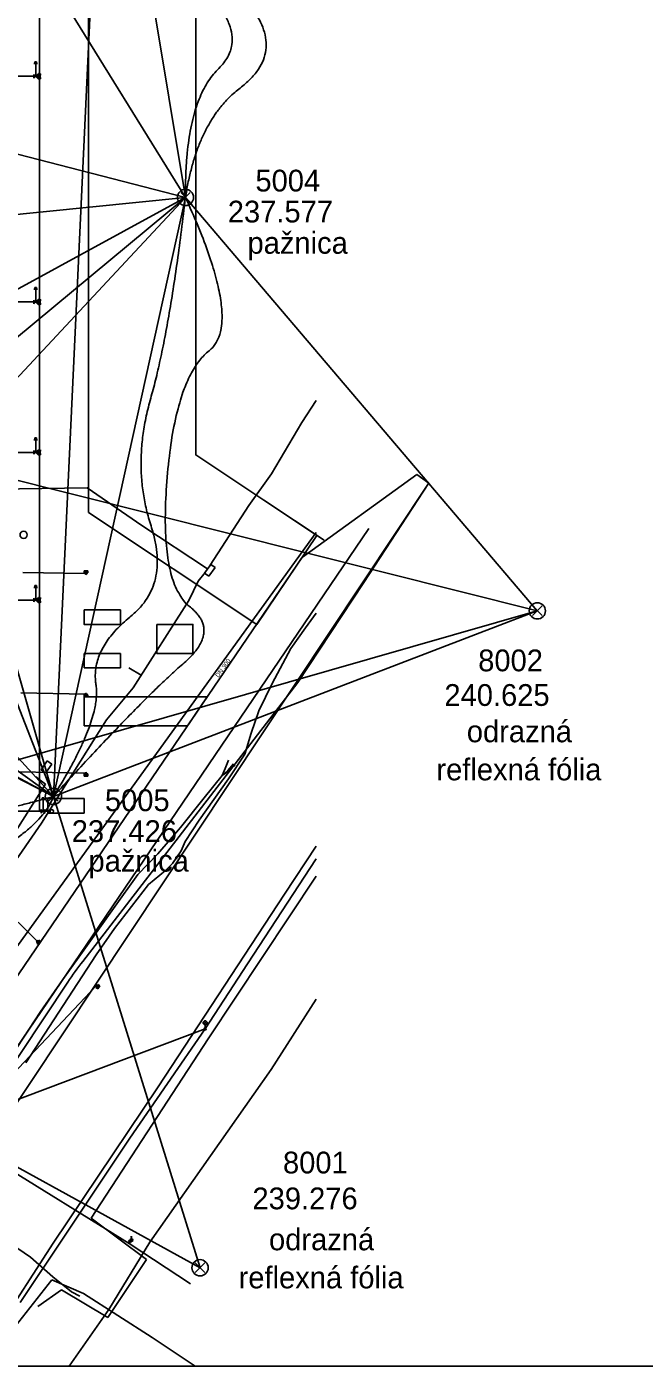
# Model space of a CAD drawing. Extents: x -264090 to -263500, y -1242327 to -1242030.
# Drawn here: x -263789.9 to -263704.8, y -1242326.6 to -1242142 of the extents above; entities that cross this region are included whole.
import ezdxf

# ---------------------------------------------------------------- set-up
doc = ezdxf.new("R2010")
doc.units = 0
for name, color, linetype in [('KFA_KOORD_SIT_a_IS_SEDA', 7, 'Continuous'), ('KFA_ZVS_BOD_CISLO', 7, 'Continuous'), ('KFA_ZVS_BOD_SYMBOL', 7, 'Continuous'), ('KFA_ZVS_BOD_VYSKA', 7, 'Continuous'), ('KFA_ZVS_NIVELACIA', 7, 'Continuous'), ('KFA_ZVS_POPIS', 7, 'Continuous'), ('KFA_ZVS_SMERY_A_DLZKY', 7, 'Continuous'), ('RAM_NA_TLAC', 7, 'Continuous')]:
    doc.layers.add(name, color=color, linetype=linetype)

msp = doc.modelspace()

# ---------------------------------------------------------------- linework, layer by layer
at = {"layer": 'KFA_KOORD_SIT_a_IS_SEDA'}
for p, q in [((-263766.58, -1242144.85), (-263766.58, -1242074.39)), ((-263788.14, -1242250.14), (-263788.14, -1242082.64)), ((-263766.58, -1242201.01), (-263766.58, -1242144.85)), ((-263788.77, -1242147.08), (-263788.89, -1242147.08)), ((-263788.77, -1242146.83), (-263788.77, -1242147.08)), ((-263788.52, -1242146.83), (-263788.77, -1242146.83)), ((-263788.64, -1242148.83), (-263788.64, -1242146.96)), ((-263788.52, -1242147.08), (-263788.52, -1242146.83)), ((-263788.52, -1242147.08), (-263788.39, -1242147.08)), ((-263788.89, -1242148.83), (-263800.59, -1242148.83)), ((-263788.89, -1242148.58), (-263788.89, -1242149.08)), ((-263788.39, -1242149.08), (-263788.89, -1242148.58)), ((-263788.89, -1242149.08), (-263788.39, -1242148.58)), ((-263788.39, -1242148.58), (-263788.39, -1242149.08)), ((-263788.39, -1242148.58), (-263787.89, -1242148.58)), ((-263788.14, -1242148.83), (-263788.39, -1242148.83)), ((-263788.39, -1242148.83), (-263788.14, -1242148.83)), ((-263788.39, -1242149.08), (-263787.89, -1242149.08)), ((-263788.27, -1242148.46), (-263788.27, -1242149.21)), ((-263788.02, -1242148.46), (-263788.27, -1242148.46)), ((-263788.02, -1242149.21), (-263788.02, -1242148.46)), ((-263788.27, -1242149.21), (-263788.02, -1242149.21)), ((-263788.77, -1242178.18), (-263788.89, -1242178.18)), ((-263788.77, -1242177.93), (-263788.77, -1242178.18)), ((-263788.52, -1242177.93), (-263788.77, -1242177.93)), ((-263788.64, -1242179.93), (-263788.64, -1242178.06)), ((-263788.52, -1242178.18), (-263788.52, -1242177.93)), ((-263788.52, -1242178.18), (-263788.39, -1242178.18)), ((-263788.89, -1242179.93), (-263800.59, -1242179.93)), ((-263788.89, -1242179.68), (-263788.89, -1242180.18)), ((-263788.39, -1242180.18), (-263788.89, -1242179.68)), ((-263788.89, -1242180.18), (-263788.39, -1242179.68)), ((-263788.39, -1242179.68), (-263788.39, -1242180.18)), ((-263788.39, -1242179.68), (-263787.89, -1242179.68)), ((-263788.14, -1242179.93), (-263788.39, -1242179.93)), ((-263788.39, -1242179.93), (-263788.14, -1242179.93)), ((-263788.39, -1242180.18), (-263787.89, -1242180.18)), ((-263788.27, -1242179.56), (-263788.27, -1242180.31)), ((-263788.02, -1242179.56), (-263788.27, -1242179.56)), ((-263788.27, -1242180.31), (-263788.02, -1242180.31)), ((-263788.02, -1242180.31), (-263788.02, -1242179.56)), ((-263751.97, -1242196.56), (-263750, -1242193.5)), ((-263756.14, -1242203.63), (-263751.97, -1242196.56)), ((-263788.77, -1242198.93), (-263788.89, -1242198.93)), ((-263788.77, -1242198.68), (-263788.77, -1242198.93)), ((-263788.52, -1242198.68), (-263788.77, -1242198.68)), ((-263788.64, -1242200.68), (-263788.64, -1242198.81)), ((-263788.52, -1242198.93), (-263788.52, -1242198.68)), ((-263788.52, -1242198.93), (-263788.39, -1242198.93)), ((-263788.89, -1242200.68), (-263800.59, -1242200.68)), ((-263788.89, -1242200.43), (-263788.89, -1242200.93)), ((-263788.39, -1242200.93), (-263788.89, -1242200.43)), ((-263788.89, -1242200.93), (-263788.39, -1242200.43)), ((-263788.39, -1242200.43), (-263788.39, -1242200.93)), ((-263788.39, -1242200.43), (-263787.89, -1242200.43)), ((-263788.14, -1242200.68), (-263788.39, -1242200.68)), ((-263788.39, -1242200.68), (-263788.14, -1242200.68)), ((-263788.27, -1242200.31), (-263788.27, -1242201.06)), ((-263788.02, -1242200.31), (-263788.27, -1242200.31)), ((-263788.02, -1242201.06), (-263788.02, -1242200.31)), ((-263788.39, -1242200.93), (-263787.89, -1242200.93)), ((-263788.27, -1242201.06), (-263788.02, -1242201.06)), ((-263758.42, -1242206.43), (-263766.58, -1242201.01)), ((-263759.28, -1242208.01), (-263756.14, -1242203.63)), ((-263736.13, -1242203.7), (-263751.89, -1242215.1)), ((-263736.13, -1242203.7), (-263734.47, -1242204.91)), ((-263815.37, -1242326.62), (-263734.49, -1242204.94)), ((-263808.34, -1242205.95), (-263781.54, -1242205.56)), ((-263781.54, -1242205.56), (-263774.03, -1242210.74)), ((-263764.6, -1242216.21), (-263759.28, -1242208.01)), ((-263757.19, -1242207.25), (-263758.42, -1242206.43)), ((-263748.89, -1242212.77), (-263757.19, -1242207.25)), ((-263806.91, -1242290.43), (-263750, -1242211.71)), ((-263794.9, -1242288.03), (-263742.74, -1242211.14)), ((-263774.03, -1242210.74), (-263764.98, -1242216.74)), ((-263798.9, -1242284.13), (-263751.86, -1242215.08)), ((-263751.89, -1242215.1), (-263751.89, -1242215.1)), ((-263781.82, -1242217.38), (-263790.41, -1242217.22)), ((-263781.97, -1242216.99), (-263781.47, -1242216.99)), ((-263781.97, -1242217.28), (-263781.97, -1242216.99)), ((-263781.97, -1242216.99), (-263781.47, -1242217.28)), ((-263781.97, -1242216.99), (-263781.47, -1242217.28)), ((-263781.47, -1242216.99), (-263781.97, -1242216.99)), ((-263781.47, -1242217.28), (-263781.97, -1242217.28)), ((-263781.47, -1242216.99), (-263781.47, -1242217.28)), ((-263781.47, -1242217.28), (-263781.47, -1242216.99)), ((-263765.31, -1242217.22), (-263766.27, -1242218.42)), ((-263765.39, -1242217.3), (-263764.49, -1242216.1)), ((-263764.79, -1242217.75), (-263765.39, -1242217.3)), ((-263765.39, -1242217.3), (-263765.39, -1242217.3)), ((-263763.89, -1242216.54), (-263764.79, -1242217.75)), ((-263764.49, -1242216.1), (-263763.89, -1242216.54)), ((-263788.77, -1242219.28), (-263788.89, -1242219.28)), ((-263788.77, -1242219.03), (-263788.77, -1242219.28)), ((-263788.52, -1242219.03), (-263788.77, -1242219.03)), ((-263788.64, -1242221.03), (-263788.64, -1242219.16)), ((-263788.52, -1242219.28), (-263788.52, -1242219.03)), ((-263788.52, -1242219.28), (-263788.39, -1242219.28)), ((-263766.27, -1242218.42), (-263767.52, -1242221.09)), ((-263743.42, -1242218.61), (-263752.52, -1242232.37)), ((-263788.89, -1242221.03), (-263800.59, -1242221.03)), ((-263788.89, -1242220.78), (-263788.89, -1242221.28)), ((-263788.39, -1242221.28), (-263788.89, -1242220.78)), ((-263788.89, -1242221.28), (-263788.39, -1242220.78)), ((-263788.39, -1242220.78), (-263788.39, -1242221.28)), ((-263788.39, -1242220.78), (-263787.89, -1242220.78)), ((-263788.14, -1242221.03), (-263788.39, -1242221.03)), ((-263788.39, -1242221.03), (-263788.14, -1242221.03)), ((-263788.27, -1242220.66), (-263788.27, -1242221.41)), ((-263788.02, -1242220.66), (-263788.27, -1242220.66)), ((-263788.02, -1242221.41), (-263788.02, -1242220.66)), ((-263767.52, -1242221.09), (-263775.23, -1242233.12)), ((-263788.39, -1242221.28), (-263787.89, -1242221.28)), ((-263788.27, -1242221.41), (-263788.02, -1242221.41)), ((-263750, -1242222.85), (-263751.46, -1242224.83)), ((-263751.46, -1242224.83), (-263753.47, -1242227.7)), ((-263781.97, -1242228.38), (-263781.97, -1242230.38)), ((-263776.97, -1242228.38), (-263781.97, -1242228.38)), ((-263776.97, -1242230.38), (-263776.97, -1242228.38)), ((-263753.47, -1242227.7), (-263756.03, -1242232.54)), ((-263781.97, -1242230.38), (-263776.97, -1242230.38)), ((-263774.12, -1242231.39), (-263775.8, -1242230.38)), ((-263781.82, -1242233.99), (-263790.71, -1242233.83)), ((-263752.52, -1242232.37), (-263782.17, -1242270.82)), ((-263775.23, -1242233.12), (-263778.87, -1242237.51)), ((-263756.03, -1242232.54), (-263757.88, -1242236.29)), ((-263781.97, -1242234.09), (-263781.47, -1242234.09)), ((-263781.97, -1242234.38), (-263781.97, -1242234.09)), ((-263781.97, -1242234.09), (-263781.47, -1242234.38)), ((-263781.97, -1242234.09), (-263781.47, -1242234.38)), ((-263781.47, -1242234.09), (-263781.97, -1242234.09)), ((-263781.47, -1242234.38), (-263781.97, -1242234.38)), ((-263781.97, -1242234.38), (-263771.97, -1242234.38)), ((-263781.97, -1242238.38), (-263781.97, -1242234.38)), ((-263781.97, -1242234.38), (-263781.97, -1242234.38)), ((-263781.47, -1242234.09), (-263781.47, -1242234.38)), ((-263781.47, -1242234.38), (-263781.47, -1242234.09)), ((-263771.97, -1242234.38), (-263765.01, -1242234.38)), ((-263765.01, -1242234.38), (-263767.74, -1242238.38)), ((-263778.87, -1242237.51), (-263787.86, -1242251.77)), ((-263757.88, -1242236.29), (-263758.95, -1242239.35)), ((-263771.97, -1242238.38), (-263781.97, -1242238.38)), ((-263767.74, -1242238.38), (-263771.97, -1242238.38)), ((-263758.95, -1242239.35), (-263759.83, -1242242.28)), ((-263787.91, -1242244.43), (-263787.06, -1242243.19)), ((-263787.06, -1242243.19), (-263786.44, -1242243.62)), ((-263762.52, -1242244.22), (-263762.07, -1242243.09)), ((-263759.83, -1242242.28), (-263762.06, -1242245.68)), ((-263781.82, -1242244.89), (-263790.91, -1242244.72)), ((-263787.29, -1242244.86), (-263787.91, -1242244.43)), ((-263787.91, -1242244.43), (-263787.91, -1242244.43)), ((-263786.44, -1242243.62), (-263787.29, -1242244.86)), ((-263781.97, -1242244.99), (-263781.47, -1242244.99)), ((-263781.97, -1242245.28), (-263781.97, -1242244.99)), ((-263781.97, -1242244.99), (-263781.47, -1242245.28)), ((-263781.97, -1242244.99), (-263781.47, -1242245.28)), ((-263781.47, -1242244.99), (-263781.97, -1242244.99)), ((-263781.47, -1242244.99), (-263781.47, -1242245.28)), ((-263781.47, -1242245.28), (-263781.47, -1242244.99)), ((-263762.95, -1242245.22), (-263762.52, -1242244.22)), ((-263762.95, -1242245.22), (-263762.18, -1242244.51)), ((-263762.95, -1242245.22), (-263762.02, -1242244.55)), ((-263762.18, -1242244.51), (-263761.39, -1242243.59)), ((-263762.02, -1242244.55), (-263761.13, -1242243.76)), ((-263793.32, -1242255.89), (-263787.3, -1242246.38)), ((-263787.3, -1242246.38), (-263788.61, -1242245.38)), ((-263781.47, -1242245.28), (-263781.97, -1242245.28)), ((-263762.06, -1242245.68), (-263766.13, -1242251.37)), ((-263765.43, -1242248.29), (-263762.95, -1242245.22)), ((-263787.77, -1242248.51), (-263787.89, -1242248.51)), ((-263787.77, -1242248.26), (-263787.77, -1242248.51)), ((-263787.52, -1242248.26), (-263787.77, -1242248.26)), ((-263787.64, -1242250.14), (-263787.64, -1242248.39)), ((-263787.52, -1242248.51), (-263787.52, -1242248.26)), ((-263787.39, -1242248.51), (-263787.52, -1242248.51)), ((-263768.68, -1242252.39), (-263765.43, -1242248.29)), ((-263924.14, -1242250.14), (-263788.14, -1242250.14)), ((-263788.14, -1242250.14), (-263787.89, -1242250.14)), ((-263788.14, -1242250.14), (-263787.89, -1242250.14)), ((-263787.89, -1242250.39), (-263787.39, -1242249.89)), ((-263787.89, -1242249.89), (-263787.89, -1242250.39)), ((-263787.39, -1242250.39), (-263787.89, -1242249.89)), ((-263787.39, -1242249.89), (-263787.39, -1242250.39)), ((-263787.39, -1242250.14), (-263786.69, -1242250.14)), ((-263787.86, -1242251.77), (-263794.54, -1242261.42)), ((-263771.82, -1242255.98), (-263768.68, -1242252.39)), ((-263766.13, -1242251.37), (-263768.04, -1242254.28)), ((-263768.04, -1242254.28), (-263768.58, -1242255.58)), ((-263774.57, -1242258.86), (-263771.82, -1242255.98)), ((-263768.58, -1242255.58), (-263769.79, -1242257.33)), ((-263750, -1242254.94), (-263754.37, -1242261.56)), ((-263769.79, -1242257.33), (-263770.75, -1242258.31)), ((-263750, -1242256.71), (-263759.47, -1242271.14)), ((-263777.94, -1242263.54), (-263774.57, -1242258.86)), ((-263770.75, -1242258.31), (-263773.12, -1242260.22)), ((-263764.86, -1242281.49), (-263750, -1242259.06)), ((-263773.12, -1242260.22), (-263777.8, -1242266.3)), ((-263754.37, -1242261.56), (-263771.77, -1242288.1)), ((-263781.56, -1242268.62), (-263777.94, -1242263.54)), ((-263788.5, -1242267.99), (-263791.06, -1242265.43)), ((-263777.8, -1242266.3), (-263780.3, -1242269.92)), ((-263788.49, -1242268.32), (-263788.21, -1242267.91)), ((-263788.21, -1242267.91), (-263788.49, -1242268.32)), ((-263788.49, -1242268.32), (-263787.97, -1242268.07)), ((-263788.49, -1242268.32), (-263787.97, -1242268.07)), ((-263788.25, -1242268.49), (-263788.49, -1242268.32)), ((-263787.97, -1242268.07), (-263788.25, -1242268.49)), ((-263788.21, -1242267.91), (-263787.97, -1242268.07)), ((-263787.97, -1242268.07), (-263788.21, -1242267.91)), ((-263784.91, -1242273.31), (-263781.56, -1242268.62)), ((-263780.3, -1242269.92), (-263790.03, -1242284.82)), ((-263759.47, -1242271.14), (-263765.29, -1242280.13)), ((-263780.35, -1242274.24), (-263808.25, -1242303.78)), ((-263795.42, -1242290.54), (-263784.21, -1242273.68)), ((-263788.05, -1242277.83), (-263784.91, -1242273.31)), ((-263780.34, -1242274.43), (-263780.06, -1242274.01)), ((-263780.06, -1242274.01), (-263780.34, -1242274.43)), ((-263780.34, -1242274.43), (-263779.82, -1242274.17)), ((-263780.34, -1242274.43), (-263779.82, -1242274.17)), ((-263780.1, -1242274.59), (-263780.34, -1242274.43)), ((-263779.82, -1242274.17), (-263780.1, -1242274.59)), ((-263780.06, -1242274.01), (-263779.82, -1242274.17)), ((-263779.82, -1242274.17), (-263780.06, -1242274.01)), ((-263756.19, -1242285.72), (-263750, -1242276.01)), ((-263791.14, -1242282.61), (-263788.05, -1242277.83)), ((-263792.97, -1242290.55), (-263765.27, -1242280.1)), ((-263765.29, -1242280.13), (-263775.66, -1242295.19)), ((-263765.49, -1242279.09), (-263765.09, -1242279.49)), ((-263765.09, -1242279.09), (-263765.49, -1242279.49)), ((-263765.29, -1242279.57), (-263765.29, -1242280.13)), ((-263781.01, -1242306.2), (-263764.86, -1242281.49)), ((-263772.92, -1242309.53), (-263756.2, -1242285.74)), ((-263756.2, -1242285.73), (-263756.19, -1242285.72)), ((-263756.2, -1242285.74), (-263756.2, -1242285.73)), ((-263771.77, -1242288.1), (-263786.26, -1242309.66)), ((-263806.91, -1242290.43), (-263775.78, -1242309.71)), ((-263775.66, -1242295.19), (-263784.7, -1242308.69)), ((-263795.49, -1242307.45), (-263789.36, -1242311.61)), ((-263773.36, -1242311.9), (-263781.01, -1242306.2)), ((-263786.26, -1242309.66), (-263797.19, -1242326.62)), ((-263784.7, -1242308.69), (-263790.78, -1242317.83)), ((-263778.59, -1242318.79), (-263772.92, -1242309.53)), ((-263775.78, -1242309.71), (-263767.31, -1242315.26)), ((-263775.61, -1242309.35), (-263775.31, -1242309.12)), ((-263775.58, -1242308.8), (-263775.33, -1242308.8)), ((-263775.46, -1242309.05), (-263775.46, -1242308.8)), ((-263789.36, -1242311.61), (-263786.29, -1242314.3)), ((-263778.69, -1242319.9), (-263773.36, -1242311.9)), ((-263792.5, -1242322.42), (-263786.42, -1242314.72)), ((-263786.42, -1242314.72), (-263782.04, -1242316.62)), ((-263786.29, -1242314.3), (-263783.7, -1242316.36)), ((-263788.34, -1242318.41), (-263785.11, -1242316.11)), ((-263785.11, -1242316.11), (-263778.69, -1242319.9)), ((-263783.7, -1242316.36), (-263782.58, -1242316.96)), ((-263782.04, -1242316.62), (-263772.58, -1242322.66)), ((-263778.59, -1242318.79), (-263784.04, -1242326.62)), ((-263772.58, -1242322.66), (-263766.65, -1242326.62))]:
    msp.add_line(p, q, dxfattribs=at)
for points in [[(-263766.58, -1242083.48), (-263766.58, -1242201.01), (-263749.88, -1242212.11), (-263758.15, -1242224.37), (-263781.36, -1242208.94), (-263781.37, -1242084.9)], [(-263781.97, -1242222.38), (-263776.97, -1242222.38), (-263776.97, -1242224.38), (-263781.97, -1242224.38)], [(-263771.97, -1242224.38), (-263766.97, -1242224.38), (-263766.97, -1242228.38), (-263771.97, -1242228.38)], [(-263786.97, -1242248.38), (-263781.97, -1242248.38), (-263781.97, -1242250.38), (-263786.97, -1242250.38)]]:
    msp.add_lwpolyline(points, close=True, dxfattribs=at)
msp.add_lwpolyline([(-263743.42, -1242218.61), (-263734.49, -1242204.94), (-263734.47, -1242204.91), (-263734.47, -1242204.91)], dxfattribs=at)
for centre, radius in [((-263790.31, -1242212.03), 0.5), ((-263781.72, -1242217.38), 0.1), ((-263781.72, -1242233.99), 0.1), ((-263781.72, -1242244.89), 0.1), ((-263786.44, -1242250.14), 0.25), ((-263788.43, -1242268.06), 0.1), ((-263780.28, -1242274.16), 0.1), ((-263765.29, -1242279.29), 0.281), ((-263765.29, -1242280.13), 0.15), ((-263775.64, -1242309.41), 0.179), ((-263775.46, -1242309.24), 0.188)]:
    msp.add_circle(centre, radius, dxfattribs=at)
msp.add_arc((-263742.57, -1242301.35), 50, 142.3688, 146.3992, dxfattribs=at)
at = {"layer": 'KFA_ZVS_BOD_SYMBOL'}
for p, q in [((-263768.66, -1242166.19), (-263767.34, -1242164.87)), ((-263767.34, -1242166.19), (-263768.66, -1242164.87)), ((-263720.17, -1242223.17), (-263718.84, -1242221.84)), ((-263718.84, -1242223.17), (-263720.17, -1242221.84)), ((-263786.87, -1242248.75), (-263785.55, -1242247.43)), ((-263785.55, -1242248.75), (-263786.87, -1242247.43)), ((-263766.66, -1242313.72), (-263765.33, -1242312.39)), ((-263765.33, -1242313.72), (-263766.66, -1242312.39))]:
    msp.add_line(p, q, dxfattribs=at)
for centre in [(-263768, -1242165.53), (-263719.5, -1242222.51), (-263786.21, -1242248.09), (-263765.99, -1242313.05)]:
    msp.add_circle(centre, 1.12, dxfattribs=at)
at = {"layer": 'KFA_ZVS_NIVELACIA'}
for points in [[(-263768, -1242165.53), (-263766.39, -1242154.95), (-263754.57, -1242145.95), (-263762.11, -1242134.38), (-263768.79, -1242126.24), (-263774.94, -1242112.5), (-263770.14, -1242105.81), (-263779.17, -1242098.02)], [(-263779.17, -1242098.02), (-263774.35, -1242108.43), (-263772.85, -1242129.58), (-263758.75, -1242143.23), (-263768.13, -1242152.33), (-263768, -1242165.53)], [(-263786.21, -1242248.09), (-263773.55, -1242234.26), (-263763.1, -1242225.35), (-263771.67, -1242218.58), (-263769.43, -1242190.31), (-263759.99, -1242182.96), (-263768, -1242165.53)], [(-263768, -1242165.53), (-263770.15, -1242183.97), (-263775.46, -1242202.57), (-263770.08, -1242218.86), (-263781.1, -1242227.76), (-263779.58, -1242237.55), (-263786.21, -1242248.09)], [(-263858.27, -1242262.29), (-263841.11, -1242267.35), (-263818.62, -1242274.1), (-263806.02, -1242261.05), (-263788.03, -1242252.95), (-263786.21, -1242248.09)], [(-263786.21, -1242248.09), (-263795.9, -1242250.78), (-263812.26, -1242253.76), (-263813.29, -1242260.92), (-263826.24, -1242266.17), (-263840.84, -1242262.69), (-263851.44, -1242261.26), (-263858.27, -1242262.29)]]:
    msp.add_open_spline(points, degree=2, dxfattribs=at)
at = {"layer": 'KFA_ZVS_SMERY_A_DLZKY'}
for p, q in [((-263786.21, -1242248.09), (-263845.52, -1242040.3)), ((-263768, -1242165.53), (-263845.52, -1242040.3)), ((-263786.21, -1242248.09), (-263854.01, -1242074.33)), ((-263786.21, -1242248.09), (-263940.79, -1242078.94)), ((-263779.17, -1242098.02), (-263786.21, -1242248.09)), ((-263779.17, -1242098.02), (-263768, -1242165.53)), ((-263786.21, -1242248.09), (-263975.49, -1242112.21)), ((-263768, -1242165.53), (-263975.49, -1242112.21)), ((-263768, -1242165.53), (-263946.28, -1242313.43)), ((-263937.6, -1242258.21), (-263768, -1242165.53)), ((-263768, -1242165.53), (-263916.9, -1242180.64)), ((-263858.27, -1242262.29), (-263768, -1242165.53)), ((-263786.21, -1242248.09), (-263768, -1242165.53)), ((-263768, -1242165.53), (-263719.5, -1242222.51)), ((-263936.8, -1242167.95), (-263786.21, -1242248.09)), ((-263936.8, -1242167.95), (-263719.5, -1242222.51)), ((-263786.21, -1242248.09), (-263916.9, -1242180.64)), ((-263858.27, -1242262.29), (-263719.5, -1242222.51)), ((-263786.21, -1242248.09), (-263719.5, -1242222.51)), ((-263786.21, -1242248.09), (-263765.99, -1242313.05)), ((-263858.27, -1242262.29), (-263765.99, -1242313.05))]:
    msp.add_line(p, q, dxfattribs=at)
at = {"layer": 'RAM_NA_TLAC'}
msp.add_lwpolyline([(-264089.66, -1242029.62), (-263499.66, -1242029.62), (-263499.66, -1242326.62), (-264089.66, -1242326.62)], close=True, dxfattribs=at)

# ---------------------------------------------------------------- texts
at = {"layer": 'KFA_KOORD_SIT_a_IS_SEDA'}
msp.add_text(' DN 300', height=0.625, rotation=54.0559, dxfattribs=at).set_placement((-263763.59, -1242231.95))
at = {"layer": 'KFA_ZVS_BOD_CISLO'}
for s, p in [('5004', (-263758.36, -1242164.71)), ('8002', (-263727.65, -1242230.84)), ('5005', (-263779.11, -1242250.12)), ('8001', (-263754.56, -1242300.05))]:
    msp.add_text(s, height=3, dxfattribs=at).set_placement(p)
at = {"layer": 'KFA_ZVS_BOD_VYSKA'}
for s, p in [('237.577', (-263762.17, -1242168.98)), ('240.625', (-263732.31, -1242235.61)), ('237.426', (-263783.68, -1242254.37)), ('239.276', (-263758.77, -1242304.99))]:
    msp.add_text(s, height=3, dxfattribs=at).set_placement(p)
at = {"layer": 'KFA_ZVS_POPIS'}
for s, p in [('pažnica', (-263759.45, -1242173.29)), ('odrazná', (-263729.22, -1242240.62)), ('reflexná fólia', (-263733.41, -1242245.87)), ('pažnica', (-263781.37, -1242258.45)), ('odrazná', (-263756.49, -1242310.64)), ('reflexná fólia', (-263760.68, -1242315.89))]:
    msp.add_text(s, height=3, dxfattribs=at).set_placement(p)

doc.saveas('drawing.dxf')
